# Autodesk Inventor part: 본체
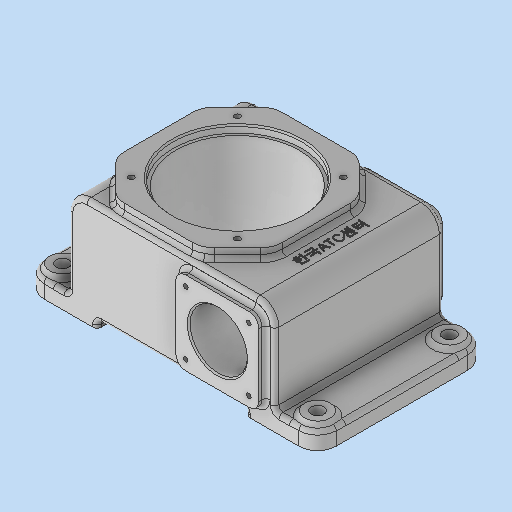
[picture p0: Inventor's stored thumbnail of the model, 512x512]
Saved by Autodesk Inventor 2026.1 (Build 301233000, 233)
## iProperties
Created: 2026-02
Part Number: 본체
Material: 일반
Document SubType Name: Modeling
Designer: PC-30
Density: 1 g/cm^3
Appearance: 기본값
Author: PC-30
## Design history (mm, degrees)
sketch "스케치2"
  geometry: L1 (59, -102)-(-59, -102); L2 (-59, -102)-(-59, 102); L3 (-59, 102)-(59, 102); L4 (59, 102)-(59, -102); L5 (59, -102)-(-59, 102); L6 (-59, -102)-(59, 102); L7 (-59, -52)-(59, -52); L8 (-59, 52)-(59, 52); 2 further points
  constraints: 16 end point, 4 point on line, 2 horizontal, 2 midpoint, 2 parallel, 2 perpendicular, 1 coincident
  dimensions: "d1" = 204 distance between parallel lines of L3 L1; "d2" = 118 distance between parallel lines of L4 L2; "d3" = 50 distance between parallel lines of L3 L8; "d4" = 50 distance between parallel lines of L1 L7
extrude "돌출1" new body sketch "스케치2" distance "d5" = 12; taper "d6" = 0 deg
node "작업 평면1"
sketch "스케치3"
  geometry: L1 (59, -72)-(-59, -72); L2 (-59, -72)-(-59, 72); L3 (-59, 72)-(59, 72); L4 (59, 72)-(59, -72); L5 (59, -72)-(-59, 72); L6 (-59, -72)-(59, 72); 1 further point
  constraints: 12 end point, 2 midpoint, 2 parallel, 1 horizontal, 1 perpendicular
  dimensions: "d8" = 118 distance between parallel lines of L2 L4; "d9" = 144 distance between parallel lines of L1 L3
extrude "돌출2" join sketch "스케치3" distance "d10" = 70; taper "d11" = 0 deg
fillet "모깎기1" dims "d31" = 13
sketch "스케치4"
  geometry: L1 (55, 43)-(55, -17); L2 (30, -42)-(-30, -42); L3 (-55, -17)-(-55, 43); L4 (-30, 68)-(30, 68); L5 (30, 68)-(55, 43); L6 (55, -17)-(30, -42); L7 (-30, -42)-(-55, -17); L8 (-55, 43)-(-30, 68); L9 (-46, -102)-(46, -102) reference; 6 further points
  constraints: 16 end point, 8 point on line, 2 horizontal, 1 midpoint, 1 vertical, 1 vertical alignment
  dimensions: "d13" = 25 distance of L4.end point (55, 68); "d14" = 25 distance of L1.start point (55, 68) (= d13); "d15" = 25 distance of L1.end point (55, -42) (= d13); "d16" = 25 distance of L2.start point (55, -42) (= d15); "d17" = 25 distance of L2.end point (-55, -42) (= d13); "d18" = 25 distance of L3.start point (-55, -42) (= d17); "d19" = 25 distance of L3.end point (-55, 68) (= d13); "d20" = 25 distance of L4.start point (-55, 68) (= d19); "d21" = 110 distance between parallel lines of L1 L3; "d23" = 55 distance from line of point (0, 13) L2; "d24" = 55 distance from line of L4 point (0, 13); "d32" = 115 distance from line of point (0, 13) L9; "d33" = 55 distance from line of L3 point (0, 13)
extrude "돌출3" join sketch "스케치4" distance "d25" = 7; taper "d26" = 0 deg
sketch "스케치5"
  geometry: L1 (-66, 11)-(-8, 11); L2 (-8, 11)-(-8, 69); L3 (-8, 69)-(-66, 69); L4 (-66, 69)-(-66, 11); L5 (-66, 11)-(-8, 69); L6 (-8, 11)-(-66, 69); L7 (-89, 0)-(-52, 0) reference; L8 (-17, 82)-(43, 82) reference; 4 further points
  constraints: 12 end point, 3 midpoint, 2 parallel, 1 horizontal, 1 perpendicular
  dimensions: "d27" = 58 distance between parallel lines of L1 L3; "d28" = 58 distance between parallel lines of L4 L2; "d29" = 40 distance from line of L7 point (-37, 40); "d36" = 50 horizontal distance of point (-37, 40) point (13, 82)
extrude "돌출4" join sketch "스케치5" distance "d34" = 5; taper "d35" = 0 deg
sketch "스케치6"
  geometry: C1 r 9 at (46, 89); C2 r 9 at (46, -89); C3 r 9 at (-46, -89); C4 r 9 at (-46, 89); A1 r 13 centre (46, 89) between (59, 89) and (46, 102) reference; A2 r 13 centre (-46, 89) between (-46, 102) and (-59, 89) reference; A3 r 13 centre (-46, -89) between (-59, -89) and (-46, -102) reference; A4 r 13 centre (46, -89) between (46, -102) and (59, -89) reference; 1 further point
  constraints: 4 centre point, 4 concentric
  dimensions: "d37" = 18 diameter of C1; "d38" = 18 diameter of C2; "d39" = 18 diameter of C4; "d40" = 18 diameter of C3
extrude "돌출5" join sketch "스케치6" distance "d49" = 3; taper "d50" = 0 deg
sketch "스케치7"
  geometry: L1 (11, -66)-(69, -66) reference; L2 (11, -8)-(11, -66) reference; C1 r 20 at (40, -37); 3 further points
  constraints: 1 centre point, 1 horizontal alignment, 1 vertical alignment
  dimensions: "d51" = 40 diameter of C1; "d123" = 29 distance from line of L1 C1.centre; "d124" = 29 distance from line of C1.centre L2
extrude "돌출6" cut sketch "스케치7" extent not by distance; stored distance "d52" = 3; taper "d53" = 0 deg
sketch "스케치8"
  geometry: L1 (-30, -42)-(30, -42) reference; L2 (55, -17)-(55, 43) reference; C1 r 45 at (0, 13); 3 further points
  constraints: 2 midpoint, 1 centre point, 1 horizontal alignment, 1 vertical alignment
  dimensions: "d54" = 90 diameter of C1
extrude "돌출7" cut sketch "스케치8" distance "d55" = 5; taper "d56" = 0 deg
sketch "스케치9"
  geometry: C1 r 45 at (0, 0) reference; 2 further points
  constraints: 1 coincident
hole "구멍1" sketch "스케치9" at (0, 0) diameter "d57" = 86; stored, may be unused: countersink angle "d61" = 90 deg, drill point angle "d63" = 0 deg; dims "d58" = 6, "d59" = 4, "d60" = 2, "d62" = 61
sketch "스케치10"
  geometry: C1 r 25 at (0, 0); C2 r 43 at (0, 0) reference; 1 further point
  constraints: 1 centre point, 1 concentric
  dimensions: "d64" = 50 diameter of C1
extrude "돌출8" join sketch "스케치10" distance "d65" = 6; taper "d66" = 0 deg
sketch "스케치11"
  geometry: C1 r 25 at (0, 0) reference; 2 further points
  constraints: 1 coincident
hole "구멍2" sketch "스케치11" at (0, 0) diameter "d67" = 40; stored, may be unused: countersink angle "d71" = 90 deg, drill point angle "d73" = 0 deg; dims "d68" = 6, "d69" = 4, "d70" = 2, "d72" = 11
feature "면 구배1" dims angle "d74" = 45 deg
sketch "스케치12"
  geometry: C1 r 9 at (0, 0) reference; C2 r 9 at (92, 0) reference; C3 r 9 at (92, -178) reference; C4 r 9 at (0, -178) reference; 5 further points
  constraints: 4 coincident
hole "구멍3" sketch "스케치12" at (0, 0), (92, 0), (92, -178), (0, -178) diameter "d75" = 9; stored, may be unused: countersink angle "d79" = 90 deg, drill point angle "d81" = 0 deg; dims "d76" = 6, "d77" = 4, "d78" = 2, "d80" = 8
sketch "스케치13"
  geometry: L1 (37, -24)-(-37, -24); L2 (-37, -24)-(-37, 50); L3 (-37, 50)-(37, 50); L4 (37, 50)-(37, -24); L5 (37, -24)-(-37, 50); L6 (-37, -24)-(37, 50); L7 (-30, -42)-(30, -42) reference; L8 (55, -17)-(55, 43) reference; 5 further points
  constraints: 12 end point, 4 midpoint, 2 parallel, 1 coincident, 1 horizontal, 1 horizontal alignment, 1 perpendicular, 1 vertical alignment
  dimensions: "d82" = 74 distance between parallel lines of L4 L2; "d83" = 74 distance between parallel lines of L3 L1
hole "구멍4" sketch "스케치13" at (-37, 50) diameter "d84" = 4.134; stored, may be unused: countersink angle "d88" = 90 deg, drill point angle "d90" = 118 deg; dims "d85" = 10, "d86" = 4, "d87" = 2, "d89" = 12
sketch "스케치14"
  geometry: L1 (18, -59)-(62, -59); L2 (62, -59)-(62, -15); L3 (62, -15)-(18, -15); L4 (18, -15)-(18, -59); L5 (18, -59)-(62, -15); L6 (62, -59)-(18, -15); L7 (12, -72)-(75, -72) reference; L8 (11, -8)-(11, -66) reference; L9 (11, -66)-(69, -66) reference; 8 further points
  constraints: 12 end point, 4 coincident, 2 midpoint, 2 parallel, 1 horizontal, 1 horizontal alignment, 1 perpendicular, 1 vertical alignment
  dimensions: "d97" = 44 distance between parallel lines of L3 L1; "d98" = 44 distance between parallel lines of L4 L2; "d125" = 29 distance from line of point (40, -37) L8; "d126" = 29 distance from line of point (40, -37) L9
hole "구멍5" sketch "스케치14" at (62, -15) diameter "d99" = 3.242; stored, may be unused: countersink angle "d103" = 90 deg, drill point angle "d105" = 118 deg; dims "d100" = 8, "d101" = 4, "d102" = 2, "d104" = 10
fillet "모깎기2" dims "d109" = 13
fillet "모깎기3" dims "d110" = 7
fillet "모깎기4" dims "d111" = 15
fillet "모깎기6" dims "d113" = 3
fillet "모깎기9" dims "d119" = 1.5
chamfer "모따기2" distance "d120" = 1; stored, may be unused: second distance "d121" = 2, angle "d122" = 45 deg
fillet "모깎기10" dims "d127" = 3
fillet "모깎기18" dims "d135" = 3
fillet "모깎기19" dims "d136" = 3
fillet "모깎기20" dims "d137" = 3
fillet "모깎기21" dims "d138" = 3
fillet "모깎기22" dims "d139" = 3
fillet "모깎기23" dims "d140" = 2.9
chamfer "모따기3" distance "d141" = 1; stored, may be unused: second distance "d142" = 2, angle "d143" = 45 deg
sketch "스케치15"
  geometry: L1 (-24.821, -48.398)-(24.954, -48.398); L2 (24.954, -48.398)-(24.954, -55.602); L3 (24.954, -55.602)-(-24.821, -55.602); L4 (-24.821, -55.602)-(-24.821, -48.398); L5 (-24.821, -52)-(24.954, -52); L6 (0.066, -48.398)-(0.066, -55.602); L7 (-55, 36.787)-(-55, -10.787) reference; 2 further points
  constraints: 5 midpoint, 4 end point, 1 vertical, 2 other
  dimensions: "d144" = 7.20489 distance between parallel lines of L3 L1; "d145" = 49.77477 distance between parallel lines of L2 L4; "d146" = 65 distance from line of point (-55, 13) L5
feature "엠보싱1" sketch "스케치15" dims "d147" = 0.5, "d148" = 0
fillet "모깎기24" dims "d149" = 3
node "솔리드1"
mirror "미러1"
pattern_linear "직사각형 패턴1" dims "d93" = 74, "d96" = 74
pattern_circular "원형 패턴1" dims angle "d107" = 360 deg
mirror "미러2"
feature "A9D066F2-1C7D-4E18-AEED-F7BC21143FA4" dims "d57" = 86, "d58" = 6, "d59" = 4, "d60" = 2, "d61" = 90 deg, "d62" = 61, "d63" = 0
other parameters: "d7" = 5
